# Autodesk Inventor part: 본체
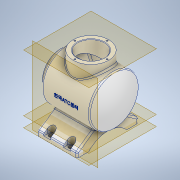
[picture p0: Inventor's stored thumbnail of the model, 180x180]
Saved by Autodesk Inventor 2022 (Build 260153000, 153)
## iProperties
Created: 2023-04
Part Number: 본체
Material: 알루미늄 6061
Document SubType Name: Modeling
Designer: Admin
Density: 2.7 g/cm^3
Appearance: 알루미늄 - 평지
Mass: 1291.82 g
Surface Area: 1062.39 cm^2
Volume: 478.451 cm^3
Author: Admin
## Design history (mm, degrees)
sketch "스케치1"
  geometry: L1 (-348.762, 0)-(521.266, 0) reference; L2 (0, -10.134)-(0, 60.805) reference; L3 (-224.472, 0)-(396.976, 0); L4 (-55.746, 0)-(-55.746, 36); L5 (-55.746, 36)-(-43.746, 36); L6 (-43.746, 36)-(-43.746, 50); L7 (-43.746, 50)-(52.59, 50); A1 r 113 centre (-48.746, 0) between (64.254, 0) and (52.59, 50); 1 further point
  constraints: 10 end point, 5 point on line, 3 perpendicular, 2 point on circle, 1 centre point, 1 vertical
  dimensions: "d3" = 72 diameter of L5 L3; "d4" = 50 distance between parallel lines of L1 L7; "d5" = 12 distance of L4.end L5.end; "d6" = 226 diameter of A1; "d7" = 48.74631 distance from line of L2 A1.centre; "d8" = 120 distance from line of A1.start L4
revolve "회전1" sketch "스케치1" stored, may be unused: angle "d9" = 360 deg
sketch "스케치2"
  geometry: L1 (-108.704, 0)-(76.451, 0) reference; L2 (0, -92.467)-(0, 110.746) reference; L3 (-34.165, -15.107)-(-67, -62); L4 (-67, -62)-(-77, -62); L5 (-77, -62)-(-77, 62); L6 (-77, 62)-(-67, 62); L7 (-67, 62)-(-34.165, 15.107); L8 (-34.165, 15.107)-(-34.165, -15.107); 1 further point
  constraints: 12 end point, 2 perpendicular, 1 horizontal, 1 parallel, 1 other
  dimensions: "d12" = 124 distance of L4.end L5.end; "d13" = 10 distance of L5.end L6.end; "d14" = 55 deg angle of L7 L6; "d15" = 55 deg angle of L3 L4; "d16" = 10 distance of L3.end L4.end; "d17" = 15.1066 distance from line of L1 L7.end; "d18" = 77 distance between parallel lines of L2 L5
extrude "돌출1" join sketch "스케치2" stored distance "d19" = 80; taper "d20" = 0 deg
node "작업 평면1"
sketch "스케치3"
  geometry: L1 (55.746, 36)-(55.746, -36) reference; L2 (79.746, 0)-(-88.254, 0) reference; L3 (0, -86.8)-(0, 86.8) reference; C1 r 36 at (-6.254, 0); C2 r 27 at (-6.254, 0); 1 further point
  constraints: 2 centre point, 1 coincident, 1 point on line
  dimensions: "d22" = 72 diameter of C1; "d23" = 62 distance from line of C1.centre L1; "d24" = 54 diameter of C2
extrude "돌출2" join sketch "스케치3" stored distance "d25" = 40; taper "d26" = 0 deg
sketch "스케치4"
  geometry: L1 (-92.77, 0)-(99.642, 0); L2 (0, -105.4)-(0, 93.4) reference; L3 (-55.746, -36)-(-55.746, 36) reference; L4 (-55.746, 27)-(-36.746, 27); L5 (-36.746, 27)-(-36.746, 40); L6 (57.254, 40.2)-(57.254, 39.154); L7 (64.254, 0)-(64.254, 54.671); L8 (-33.746, 43)-(46.723, 43); L9 (56.861, 40.2)-(57.254, 40.2); L10 (-55.746, 27)-(-55.746, 0); L11 (-116.841, 0)-(170.726, 0); A1 r 113 centre (-48.746, 0) between (52.59, -50) and (52.59, 50) reference; A2 r 113 centre (-55.746, 0) between (57.254, 0) and (49.518, 41.091); A3 r 3 centre (-33.746, 40) between (-33.746, 43) and (-36.746, 40); A4 r 3 centre (46.723, 40) between (49.518, 41.091) and (46.723, 43); 6 further points
  constraints: 18 end point, 10 point on circle, 6 tangent, 4 perpendicular, 3 centre point, 3 point on line, 2 horizontal, 1 equal radius, 1 vertical, 6 other
  dimensions: "d27" = 7 distance between parallel lines of L6 L7; "d28" = 226 diameter of A2; "d29" = 27 distance of the line from the sketch origin of L4; "d30" = 43 distance of the line from the sketch origin of L8; "d31" = 19 distance of L4.start L4.end; "d32" = 3 radius of A3
revolve "회전2" sketch "스케치4" stored, may be unused: angle "d33" = 360 deg
sketch "스케치5"
  geometry: L1 (-64.144, -60)-(74.974, -60); L2 (-62, -77)-(62, -77) reference; L3 (-91.968, 0)-(102.797, 0) reference; L4 (0, -210.029)-(0, 110.838) reference; A1 r 52.096 centre (0, -112.096) between (-38.5, -77) and (38.5, -77); 1 further point
  constraints: 3 point on line, 2 end point, 2 point on circle, 1 centre point, 1 horizontal, 1 tangent
  dimensions: "d34" = 17 distance between parallel lines of L2 L1; "d35" = 77 distance of A1.start A1.end
extrude "돌출3" cut sketch "스케치5" distance "d36" = 100; taper "d37" = 0 deg
sketch "스케치6"
  geometry: C1 r 36 at (-6.254, 0) reference; C2 r 27 at (-6.254, 0); 1 further point
  constraints: 1 centre point, 1 coincident
  dimensions: "d38" = 54 diameter of C2
extrude "돌출4" cut sketch "스케치6" distance "d39" = 40; taper "d40" = 0 deg
sketch "스케치7"
  geometry: L1 (-86, 0)-(82, 0) reference; L2 (-6.254, 86.8)-(-6.254, -86.8) reference; C1 r 27 at (0, 0) reference; A1 r 32.5 centre (0, 0) between (32.5, 0) and (0, 32.5); 3 further points
  constraints: 4 point on circle, 3 point on line, 1 centre point, 1 coincident
  dimensions: "d41" = 65 diameter of A1; "d42" = 32.5 distance from line of L1 point (0, -32.5); "d43" = 32.5 distance from line of L1 A1.end
hole "구멍1" sketch "스케치7" at (32.5, 0), (0, 32.5), (-32.5, 0), (0, -32.5) diameter "d44" = 3.242; stored, may be unused: countersink angle "d48" = 90 deg, drill point angle "d50" = 118 deg; dims "d45" = 8, "d46" = 4, "d47" = 2, "d49" = 10
sketch "스케치8"
  geometry: L1 (0, -105.4)-(0, 93.4) reference; L2 (-86.8, 0)-(86.8, 0) reference; A1 r 32.5 centre (0, 0) between (0, 32.5) and (-32.5, 0); 3 further points
  constraints: 4 point on circle, 4 point on line, 1 centre point, 1 coincident
  dimensions: "d51" = 65 diameter of A1
hole "구멍2" sketch "스케치8" at (0, 32.5), (-32.5, 0), (0, -32.5), (32.5, 0) diameter "d52" = 3.242; stored, may be unused: countersink angle "d56" = 90 deg, drill point angle "d58" = 118 deg; dims "d53" = 8, "d54" = 4, "d55" = 2, "d57" = 10
node "작업 평면2"
sketch "스케치9"
  geometry: L1 (-55.746, -36)-(-55.746, 36) reference; L2 (-79.746, 0)-(88.254, 0) reference; 2 further points
  constraints: 1 point on line, 1 other
  dimensions: "d60" = 62 distance from line of L1 point (6.254, 0)
feature "엠보싱1" sketch "스케치9" dims "d3" = 72, "d4" = 50, "d5" = 12, "d6" = 226, "d7" = 48.74631, "d8" = 120, "d61" = 0.5, "d62" = 0
node "작업 평면3"
sketch "스케치11"
  geometry: L1 (0, 124)-(80, 124) reference; L2 (0, 0)-(80, 0) reference; L3 (0, 100.5)-(0, 124) reference; L4 (0, 0)-(0, 23.5) reference; 5 further points
  dimensions: "d72" = 8 distance from line of L1 point (20, 116); "d73" = 8 distance from line of L1 point (60, 116); "d74" = 8 distance from line of L2 point (20, 8); "d75" = 8 distance from line of L2 point (60, 8); "d76" = 40 distance of point (60, 116) point (20, 116); "d77" = 40 distance of point (60, 8) point (20, 8); "d78" = 20 distance from line of L3 point (20, 116); "d79" = 20 distance from line of L4 point (20, 8)
hole "구멍3" sketch "스케치11" at (20, 116), (60, 116), (20, 8), (60, 8) diameter "d80" = 9; stored, may be unused: countersink angle "d84" = 90 deg, drill point angle "d86" = 0 deg; dims "d81" = 8, "d82" = 4, "d83" = 2, "d85" = 6
node "작업 평면4"
sketch "스케치12"
  geometry: L1 (-27, 54)-(-27, 62); L2 (40, 62)-(-40, 62) reference; L3 (-13, 54)-(-13, 62); L4 (-13, 62)-(-27, 62); L5 (13, 54)-(13, 62); L6 (13, 62)-(27, 62); L7 (27, 62)-(27, 54); L8 (-27, -54)-(-27, -62); L9 (40, -62)-(-40, -62) reference; L10 (-13, -54)-(-13, -62); L11 (-13, -62)-(-27, -62); L12 (13, -54)-(13, -62); L13 (27, -62)-(27, -54); L14 (27, -62)-(13, -62); C1 r 4.5 at (-20, 54) reference; C2 r 4.5 at (20, 54) reference; C3 r 4.5 at (-20, -54) reference; C4 r 4.5 at (20, -54) reference; A1 r 7 centre (-20, 54) between (-27, 54) and (-13, 54); A2 r 7 centre (20, 54) between (13, 54) and (27, 54); A3 r 7 centre (-20, -54) between (-27, -54) and (-13, -54); A4 r 7 centre (20, -54) between (13, -54) and (27, -54); 7 further points
  constraints: 24 end point, 14 point on line, 8 point on circle, 4 centre point, 4 coincident, 4 perpendicular, 4 tangent, 2 vertical
  dimensions: "d88" = 14 diameter of A1; "d89" = 14 diameter of A2; "d90" = 14 diameter of A3; "d91" = 14 diameter of A4
extrude "돌출5" cut sketch "스케치12" distance "d92" = 21; taper "d93" = 0 deg
chamfer "모따기1" distance "d94" = 1; stored, may be unused: second distance "d95" = 2, angle "d96" = 45 deg
fillet "모깎기1" dims "d97" = 3
chamfer "모따기2" distance "d98" = 1; stored, may be unused: second distance "d99" = 2, angle "d100" = 45 deg
node "솔리드1"
feature "A9D066F2-1C7D-4E18-AEED-F7BC21143FA4" dims "d80" = 9, "d81" = 8, "d82" = 4, "d83" = 2, "d84" = 90 deg, "d85" = 6, "d86" = 0
other parameters: "d21" = 65, "d87" = -71
